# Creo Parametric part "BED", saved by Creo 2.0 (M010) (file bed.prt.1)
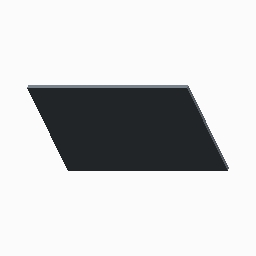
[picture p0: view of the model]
Units: Inch lbm Second (Pro/E Default); INCH, POUND, SECS

Created from: INLBS_PART_SOLID.PRT

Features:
  1. datum plane "RIGHT"
  2. datum plane "TOP"
  3. datum plane "FRONT"
  4. coordinate system
  5. sketch "Sketch 1"
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
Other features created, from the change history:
  extrusion "Extrude 1"

Surfaces: 9 plane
